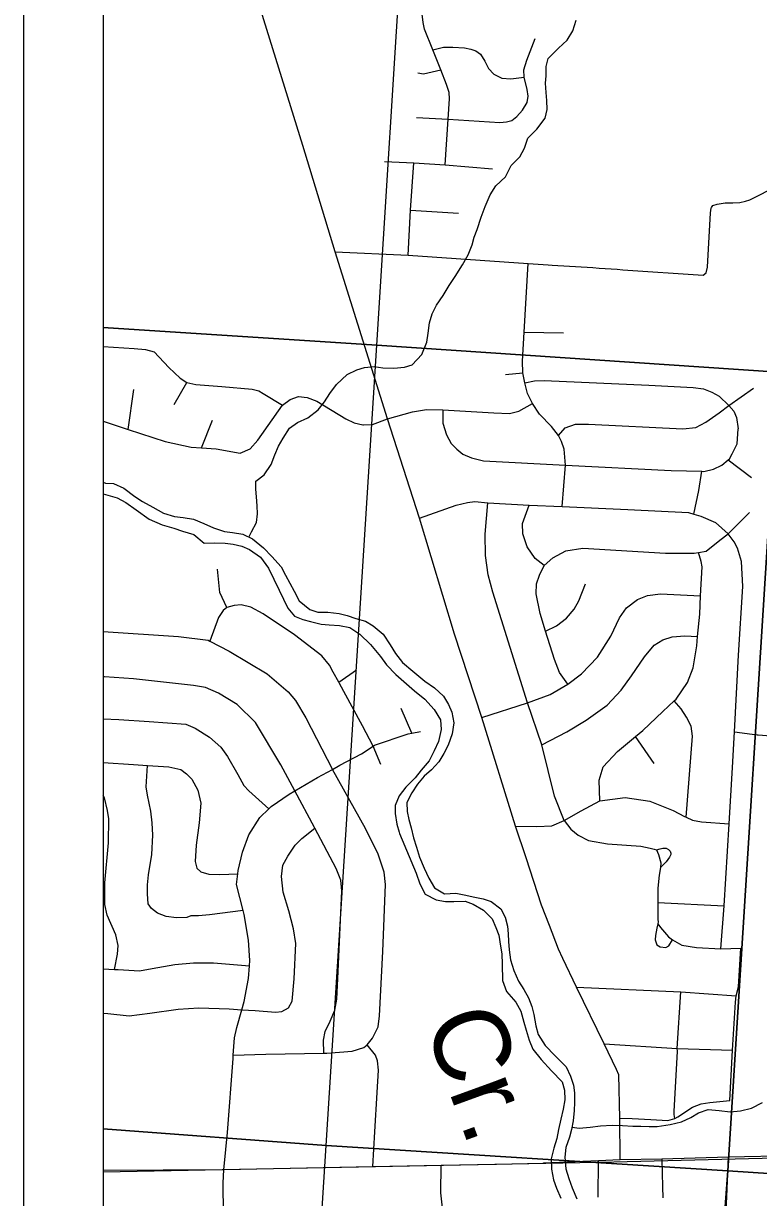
# Model space of a CAD drawing. Extents: x 0 to 34, y 0 to 22.
# Drawn here: x 2 to 2.921, y 19.283 to 20.754 of the extents above; entities that cross this region are included whole.
import ezdxf

# ---------------------------------------------------------------- set-up
doc = ezdxf.new("R2010")
doc.units = 0
for name, color, linetype in [('GM_X_City_Street', 7, 'Continuous'), ('GM_X_Corporation', 7, 'Continuous'), ('GM_X_County_Road', 7, 'Continuous'), ('GM_X_Minor_River', 7, 'Continuous'), ('GM_X_Minor_River_Text', 7, 'Continuous'), ('GM_X_Rail_Line', 7, 'Continuous'), ('GM_X_State_Route', 7, 'Continuous'), ('GM_X_Township_Road', 7, 'Continuous'), ('GM_X_US_Route', 7, 'Continuous'), ('SH_Data', 7, 'Continuous')]:
    doc.layers.add(name, color=color, linetype=linetype)

msp = doc.modelspace()

# ---------------------------------------------------------------- linework, layer by layer
at = {"layer": 'GM_X_City_Street'}
for p, q in [((2.4923, 20.6359), (2.5319, 20.6335)), ((2.485, 20.5198), (2.5451, 20.5157)), ((2.6272, 20.3667), (2.6764, 20.366)), ((2.6039, 20.3136), (2.6255, 20.316)), ((2.1888, 20.2761), (2.2045, 20.3035)), ((2.1313, 20.245), (2.1382, 20.2948)), ((2.8837, 20.275), (2.9145, 20.2967)), ((2.2231, 20.2218), (2.2369, 20.2565)), ((2.883, 20.207), (2.9121, 20.1847)), ((2.8829, 20.1141), (2.9096, 20.1408)), ((2.3949, 19.9284), (2.4171, 19.9438)), ((2.4864, 19.8644), (2.4731, 19.8953)), ((2.7901, 19.8263), (2.7668, 19.8601)), ((2.4479, 19.8249), (2.4382, 19.848)), ((2.7948, 19.6522), (2.8777, 19.6478)), ((2.72, 19.2831), (2.7206, 19.3289)), ((2.8811, 19.2837), (2.8832, 19.3334)), ((2.8794, 19.244), (2.8811, 19.2837))]:
    msp.add_line(p, q, dxfattribs=at)
for points in [[(2.5283, 20.5763), (2.5319, 20.6335), (2.5338, 20.6593), (2.5332, 20.6669), (2.5301, 20.6771), (2.523, 20.6955), (2.513, 20.7205), (2.5023, 20.7462), (2.5007, 20.7549), (2.4996, 20.7652), (2.5015, 20.7814), (2.4997, 20.8003), (2.5032, 20.8192)], [(2.5319, 20.6335), (2.5968, 20.6293), (2.605, 20.6301), (2.6118, 20.632), (2.6181, 20.637), (2.6252, 20.6448), (2.631, 20.6546), (2.6323, 20.6624), (2.6312, 20.6708), (2.6273, 20.6863), (2.627, 20.6953), (2.6307, 20.7074), (2.641, 20.7345)], [(2.513, 20.7205), (2.5264, 20.7239), (2.538, 20.7239), (2.5527, 20.7231), (2.5606, 20.7213), (2.5669, 20.7192), (2.5727, 20.715), (2.5779, 20.7063), (2.5826, 20.6971), (2.5892, 20.69), (2.5994, 20.685), (2.6105, 20.6842), (2.6273, 20.6863)], [(2.4939, 20.6915), (2.5012, 20.6905), (2.523, 20.6955)], [(2.4525, 20.5805), (2.4889, 20.5789), (2.5283, 20.5763), (2.5876, 20.5716)], [(2.4818, 20.4634), (2.485, 20.5198), (2.4889, 20.5789)], [(2.6749, 20.1482), (2.679, 20.2), (2.6774, 20.2201), (2.6741, 20.2299), (2.6704, 20.2372), (2.6615, 20.2486), (2.6463, 20.2642), (2.6378, 20.2772), (2.6316, 20.2899), (2.628, 20.3034), (2.6255, 20.316), (2.6251, 20.3303), (2.6272, 20.3667), (2.6325, 20.4528)], [(2.1, 20.3486), (2.1387, 20.3464), (2.153, 20.3449), (2.1636, 20.342), (2.182, 20.3226), (2.1964, 20.3093), (2.2045, 20.3035), (2.2159, 20.3012), (2.2483, 20.2985), (2.2865, 20.2953), (2.2947, 20.2932), (2.3003, 20.29), (2.3246, 20.2752)], [(2.628, 20.3034), (2.6402, 20.3058), (2.6525, 20.3062), (2.7834, 20.3003), (2.8392, 20.2974), (2.8521, 20.2956), (2.8625, 20.2915), (2.8715, 20.2864), (2.8837, 20.275), (2.89, 20.2678), (2.8932, 20.26), (2.8955, 20.2455)], [(2.1, 20.2554), (2.1313, 20.245), (2.1775, 20.2296), (2.2102, 20.2227), (2.2231, 20.2218), (2.2416, 20.2204), (2.2715, 20.2152), (2.2841, 20.2205), (2.2935, 20.2315), (2.3246, 20.2752), (2.334, 20.2825), (2.3446, 20.2862), (2.3556, 20.285), (2.3674, 20.2805), (2.4038, 20.258), (2.4144, 20.2531), (2.425, 20.2507), (2.426, 20.2507)], [(2.4561, 20.258), (2.4875, 20.267), (2.5051, 20.2699), (2.5255, 20.2695), (2.5892, 20.2658), (2.6088, 20.265), (2.6206, 20.2678), (2.6378, 20.2772)], [(2.6704, 20.2372), (2.6785, 20.2471), (2.6918, 20.2514), (2.7077, 20.2513), (2.8259, 20.2457), (2.8422, 20.2472), (2.8548, 20.2538), (2.8714, 20.2655), (2.8837, 20.275)], [(2.426, 20.2507), (2.4373, 20.2511), (2.4561, 20.258)], [(2.5255, 20.2695), (2.5255, 20.2527), (2.53, 20.238), (2.5357, 20.2274), (2.543, 20.2201), (2.5504, 20.2139), (2.5611, 20.2094), (2.5765, 20.2054), (2.679, 20.2), (2.8114, 20.1933), (2.85, 20.1924), (2.8526, 20.1923), (2.8644, 20.195), (2.8751, 20.2001), (2.883, 20.207), (2.8844, 20.2082), (2.8879, 20.2142), (2.8943, 20.2269), (2.8955, 20.2455)], [(2.8398, 20.1388), (2.846, 20.1682), (2.85, 20.1924)], [(2.4961, 20.1339), (2.5422, 20.1498), (2.5561, 20.1535), (2.5655, 20.1547), (2.5818, 20.1531), (2.6337, 20.1502), (2.6749, 20.1482), (2.7573, 20.1445), (2.8332, 20.1408), (2.8398, 20.1388), (2.8486, 20.1362), (2.8669, 20.1281), (2.8829, 20.1141)], [(2.6772, 19.7548), (2.6651, 19.7853), (2.6496, 19.8497), (2.6316, 19.9024), (2.5879, 20.0408), (2.5822, 20.0628), (2.579, 20.0869), (2.5786, 20.1135), (2.5818, 20.1531)], [(2.6524, 20.0743), (2.6409, 20.0833), (2.631, 20.0976), (2.6258, 20.114), (2.6253, 20.127), (2.6337, 20.1502)], [(2.6524, 20.0743), (2.6632, 20.0842), (2.6793, 20.0929), (2.701, 20.0962), (2.8044, 20.0898), (2.8403, 20.0897), (2.8459, 20.0907), (2.8555, 20.0924), (2.8725, 20.106), (2.8829, 20.1141)], [(2.8738, 19.5941), (2.8777, 19.6478), (2.884, 19.7506), (2.8883, 19.8212), (2.8907, 19.8659), (2.8958, 19.9619), (2.9013, 20.0479), (2.8994, 20.0795), (2.8945, 20.0963), (2.8902, 20.104), (2.8829, 20.1141)], [(2.722, 19.7794), (2.7212, 19.8056), (2.7261, 19.8222), (2.7444, 19.8415), (2.7668, 19.8601), (2.776, 19.8676), (2.8011, 19.8913), (2.8154, 19.9047), (2.8178, 19.9068), (2.8319, 19.9278), (2.8391, 19.9462), (2.8436, 19.9738), (2.8446, 19.9856), (2.8472, 20.0136), (2.8483, 20.0363), (2.8501, 20.0727), (2.8491, 20.0796), (2.8459, 20.0907)], [(2.2549, 20.0216), (2.2459, 20.0407), (2.2432, 20.0697)], [(2.6819, 19.9256), (2.6715, 19.9405), (2.6651, 19.9566), (2.6541, 19.992), (2.6472, 20.0144), (2.6425, 20.0388), (2.6428, 20.0513), (2.6465, 20.0622), (2.6524, 20.0743)], [(2.6541, 19.992), (2.668, 19.9987), (2.6803, 20.0086), (2.69, 20.0198), (2.6956, 20.0303), (2.704, 20.0513)], [(2.5741, 19.884), (2.6316, 19.9024), (2.6598, 19.9126), (2.6819, 19.9256), (2.699, 19.9387), (2.719, 19.9595), (2.7358, 19.9857), (2.7468, 20.0089), (2.7554, 20.0212), (2.7693, 20.0318), (2.7819, 20.0367), (2.7983, 20.0391), (2.8483, 20.0363)], [(2.4382, 19.848), (2.4249, 19.8734), (2.4119, 19.8972), (2.3959, 19.9265), (2.3949, 19.9284), (2.388, 19.9407), (2.3833, 19.9496), (2.3737, 19.9612), (2.3396, 19.9875), (2.3005, 20.0139), (2.2848, 20.0223), (2.2728, 20.0252), (2.2641, 20.0243), (2.2549, 20.0216), (2.2503, 20.0182), (2.2444, 20.0092), (2.2334, 19.9796)], [(2.1, 19.9919), (2.1943, 19.9854), (2.2313, 19.9807), (2.2334, 19.9796), (2.2578, 19.9671), (2.3055, 19.9386), (2.3318, 19.9163), (2.341, 19.9051), (2.3537, 19.8835), (2.387, 19.819)], [(2.6496, 19.8497), (2.6807, 19.8658), (2.7049, 19.8808), (2.7314, 19.8995), (2.7489, 19.9184), (2.7618, 19.936), (2.7782, 19.9599), (2.7903, 19.9744), (2.801, 19.9813), (2.8128, 19.9852), (2.8284, 19.9863), (2.8446, 19.9856)], [(2.3762, 19.4635), (2.3758, 19.4796), (2.3779, 19.4906), (2.3843, 19.5037), (2.3899, 19.5173), (2.3925, 19.5312), (2.3941, 19.5658), (2.3988, 19.667), (2.3976, 19.68), (2.3919, 19.6949), (2.3649, 19.7452), (2.3644, 19.7461), (2.3399, 19.792), (2.3224, 19.8246), (2.2908, 19.8778), (2.2679, 19.9004), (2.2444, 19.9143), (2.228, 19.9216), (2.2129, 19.9242), (2.1379, 19.9325), (2.1016, 19.935), (2.1, 19.9348)], [(2.8301, 19.7591), (2.8382, 19.8604), (2.8366, 19.873), (2.8308, 19.8845), (2.8239, 19.8949), (2.8154, 19.9047)], [(2.1, 19.8825), (2.1196, 19.8813), (2.1574, 19.8789), (2.2034, 19.8755), (2.215, 19.8706), (2.2329, 19.8595), (2.2473, 19.8466), (2.2554, 19.835), (2.2684, 19.8127), (2.2761, 19.7988), (2.2823, 19.7922), (2.3072, 19.7695)], [(2.8907, 19.8659), (2.9193, 19.8623), (2.9203, 19.8621), (2.9365, 19.861), (2.9444, 19.8604), (2.9653, 19.8622), (2.9741, 19.8665), (2.9811, 19.8739)], [(2.2509, 19.2245), (2.2501, 19.3005), (2.2511, 19.3175), (2.2514, 19.3213), (2.2554, 19.3642), (2.2625, 19.4566), (2.2628, 19.4607), (2.2643, 19.4828), (2.2673, 19.4956), (2.2735, 19.5179), (2.2764, 19.5281), (2.282, 19.5568), (2.2831, 19.5727), (2.2836, 19.5795), (2.282, 19.605), (2.2763, 19.6371), (2.2751, 19.642), (2.267, 19.6749), (2.2685, 19.688), (2.269, 19.6923), (2.2744, 19.7153), (2.2825, 19.7368), (2.2963, 19.7585), (2.3072, 19.7695), (2.3102, 19.7725), (2.3329, 19.7879), (2.3399, 19.792), (2.3685, 19.8087), (2.387, 19.819), (2.3965, 19.8243), (2.4233, 19.8385), (2.4382, 19.848), (2.4398, 19.8491), (2.4821, 19.8636), (2.4864, 19.8644), (2.4973, 19.8666)], [(2.1, 19.8275), (2.1379, 19.8251), (2.1553, 19.8239), (2.1821, 19.8221), (2.1971, 19.8187), (2.2042, 19.8132), (2.2108, 19.8069), (2.2184, 19.7931), (2.2222, 19.7766), (2.2201, 19.752), (2.2164, 19.724), (2.2152, 19.7035), (2.2172, 19.6951), (2.2224, 19.6908), (2.2322, 19.6875), (2.2458, 19.6872), (2.2685, 19.688)], [(2.2751, 19.642), (2.2332, 19.6366), (2.2192, 19.6354), (2.2097, 19.6353), (2.2048, 19.6335), (2.1919, 19.6331), (2.1787, 19.6346), (2.1679, 19.639), (2.1604, 19.6445), (2.1564, 19.6507), (2.1552, 19.6629), (2.1555, 19.6743), (2.1565, 19.6868), (2.1606, 19.7125), (2.1619, 19.7364), (2.1611, 19.752), (2.1596, 19.7668), (2.1555, 19.7867), (2.1535, 19.797), (2.1553, 19.8239)], [(2.4308, 19.4737), (2.4374, 19.4823), (2.4442, 19.4962), (2.4461, 19.5102), (2.4503, 19.5906), (2.4534, 19.6748), (2.4519, 19.69), (2.4445, 19.7126), (2.4283, 19.7449), (2.387, 19.819)], [(2.114, 19.5683), (2.1179, 19.5875), (2.1185, 19.5981), (2.1158, 19.6118), (2.1047, 19.6364), (2.102, 19.6498), (2.1019, 19.6767), (2.1065, 19.7271), (2.1068, 19.7571), (2.1052, 19.7674), (2.1014, 19.7835), (2.1, 19.7868)], [(2.6165, 19.748), (2.6431, 19.7475), (2.662, 19.7482), (2.6772, 19.7548), (2.6987, 19.767), (2.722, 19.7794), (2.7539, 19.7839), (2.7848, 19.7793), (2.814, 19.7676), (2.8282, 19.76), (2.8301, 19.7591), (2.8383, 19.7552), (2.8496, 19.7534), (2.884, 19.7506)], [(2.1, 19.5134), (2.1055, 19.513), (2.1326, 19.51), (2.1581, 19.5136), (2.1937, 19.5187), (2.2195, 19.5204), (2.2576, 19.519), (2.2735, 19.5179), (2.2901, 19.5167), (2.3157, 19.5149), (2.3237, 19.5155), (2.3321, 19.5202), (2.3365, 19.5285), (2.339, 19.5565), (2.3412, 19.6009), (2.3383, 19.6192), (2.3324, 19.6417), (2.3254, 19.6651), (2.3232, 19.6849), (2.3251, 19.6989), (2.331, 19.7101), (2.3404, 19.7239), (2.3486, 19.7325), (2.3649, 19.7452)], [(2.6772, 19.7548), (2.6857, 19.7442), (2.695, 19.7367), (2.708, 19.73), (2.7318, 19.7256), (2.7736, 19.7226), (2.7853, 19.7203), (2.79, 19.7191), (2.793, 19.7181), (2.7976, 19.7194), (2.8011, 19.7201), (2.8029, 19.7203), (2.8053, 19.7201), (2.8082, 19.7185), (2.8102, 19.7164), (2.8111, 19.7138), (2.8112, 19.7122), (2.8092, 19.7088), (2.805, 19.7031), (2.8026, 19.7006), (2.7983, 19.6962)], [(2.793, 19.7181), (2.7955, 19.7125), (2.7984, 19.702), (2.7983, 19.6962), (2.7966, 19.6864), (2.7947, 19.6701), (2.7948, 19.6522), (2.7949, 19.6462), (2.7949, 19.631), (2.7952, 19.6279), (2.7946, 19.6253), (2.7935, 19.62), (2.7918, 19.6109), (2.7916, 19.6052), (2.7937, 19.5991), (2.7978, 19.5967), (2.8046, 19.5958), (2.8085, 19.598), (2.8132, 19.6054)], [(2.7946, 19.6253), (2.798, 19.621), (2.8058, 19.6121), (2.808, 19.609), (2.8132, 19.6054), (2.8247, 19.5987), (2.8432, 19.5956), (2.8738, 19.5941), (2.8987, 19.5949)], [(2.8848, 19.4042), (2.8881, 19.467), (2.8922, 19.5271), (2.893, 19.5352), (2.8959, 19.5467), (2.8987, 19.5949)], [(2.1, 19.5691), (2.114, 19.5683), (2.1185, 19.5681), (2.1453, 19.5667), (2.1613, 19.5693), (2.1898, 19.5747), (2.2129, 19.5767), (2.2382, 19.5765), (2.2831, 19.5727)], [(2.6929, 19.5463), (2.8236, 19.5401), (2.893, 19.5352)], [(2.8162, 19.3815), (2.8151, 19.3867), (2.8152, 19.3903), (2.8192, 19.4659), (2.819, 19.4691), (2.8236, 19.5401)], [(2.2628, 19.4607), (2.3035, 19.4621), (2.3762, 19.4635), (2.3799, 19.4636), (2.4117, 19.4658), (2.4266, 19.4704), (2.4308, 19.4737)], [(2.4377, 19.3214), (2.4403, 19.3649), (2.443, 19.4142), (2.4448, 19.4422), (2.4436, 19.454), (2.4411, 19.4609), (2.4308, 19.4737)], [(2.7276, 19.4749), (2.819, 19.4691), (2.8881, 19.467)], [(2.747, 19.3821), (2.7624, 19.3814), (2.7859, 19.3801), (2.8073, 19.379), (2.8162, 19.3815), (2.8199, 19.3835), (2.8384, 19.3956), (2.8491, 19.3999), (2.8597, 19.4015), (2.8848, 19.4042)], [(2.525, 19.2698), (2.5227, 19.2884), (2.5232, 19.3231)]]:
    msp.add_lwpolyline(points, dxfattribs=at)
at = {"layer": 'GM_X_Corporation'}
for points in [[(4.3071, 20.9), (2.1, 20.9), (2.1, 14.1), (3.0169, 14.1), (3.0406, 14.4484), (3.1026, 15.287), (3.1745, 16.2606), (2.934, 16.2765), (2.366, 16.3159), (2.2862, 16.3208), (2.1768, 16.323), (2.2478, 17.3472), (2.3155, 18.3567), (3.8153, 18.2543), (3.8503, 18.7566), (3.8611, 18.9124), (3.8924, 19.3621), (3.9019, 19.4987), (3.9133, 19.6628), (3.9816, 20.645), (3.9912, 20.7822), (4.2975, 20.7549)], [(2.1177, 20.9), (2.1, 20.9), (2.1, 20.3725), (2.4427, 20.3504), (2.4759, 20.8769), (2.3657, 20.8848)], [(2.4759, 20.8769), (3.2845, 20.8293), (3.4815, 20.8174), (3.4452, 20.283), (2.9456, 20.3167), (2.4427, 20.3504)], [(2.1, 20.3725), (2.1, 19.3686), (2.3794, 19.3479), (2.4427, 20.3504)], [(2.4427, 20.3504), (2.9456, 20.3167), (2.8825, 19.3159), (2.3794, 19.3479)], [(2.9456, 20.3167), (3.4452, 20.283), (3.3789, 19.2835), (2.8825, 19.3159)], [(2.1, 19.3686), (2.1, 18.3755), (2.3165, 18.3624), (2.3794, 19.3479)], [(2.3794, 19.3479), (2.8825, 19.3159), (2.8093, 18.3281), (2.3165, 18.3624)], [(2.8825, 19.3159), (3.3789, 19.2835), (3.3148, 18.2914), (2.8093, 18.3281)]]:
    msp.add_lwpolyline(points, close=True, dxfattribs=at)
for points in [[(3.8151, 18.2549), (3.8501, 18.7572), (3.8609, 18.9129), (3.8918, 19.3576), (3.8924, 19.3656), (3.9015, 19.4967), (3.9015, 19.497), (3.9131, 19.6633), (3.9131, 19.6638), (3.9335, 19.9563), (3.9417, 20.0742), (3.9814, 20.6455), (3.9909, 20.7828), (4.2973, 20.7554), (4.3068, 20.9), (2.1, 20.9), (2.1, 14.1)], [(3.8151, 18.2549), (3.8501, 18.7572), (3.8609, 18.9129), (3.8918, 19.3576), (3.8924, 19.3656), (3.9015, 19.4967), (3.9015, 19.497), (3.9131, 19.6633), (3.9131, 19.6638), (3.9335, 19.9563), (3.9417, 20.0742), (3.9814, 20.6455), (3.9909, 20.7828), (3.2798, 20.8248), (2.7336, 20.8606), (2.2596, 20.8916), (2.1, 20.8993), (2.1, 16.3272)], [(2.1, 20.8991), (2.1, 17.7516)]]:
    msp.add_lwpolyline(points, dxfattribs=at)
at = {"layer": 'GM_X_County_Road'}
msp.add_line((2.7475, 19.3301), (2.747, 19.3821), dxfattribs=at)
for points in [[(2.6759, 19.582), (2.6704, 19.5936), (2.659, 19.6234), (2.6492, 19.6488), (2.63, 19.708), (2.6165, 19.748), (2.5741, 19.884), (2.5402, 19.9885), (2.4961, 20.1339), (2.4561, 20.258), (2.3903, 20.4675), (2.3499, 20.6006), (2.2823, 20.8191), (2.2616, 20.8854)], [(2.747, 19.3821), (2.746, 19.4364), (2.743, 19.443), (2.7276, 19.4749), (2.6929, 19.5463), (2.6759, 19.582)]]:
    msp.add_lwpolyline(points, dxfattribs=at)
at = {"layer": 'GM_X_Minor_River'}
for points in [[(2.2825, 20.11), (2.2856, 20.1166), (2.2921, 20.1283), (2.2933, 20.1393), (2.2926, 20.1492), (2.2919, 20.1606), (2.2912, 20.1701), (2.2909, 20.1799), (2.3016, 20.1882), (2.3103, 20.2011), (2.315, 20.2132), (2.3196, 20.2238), (2.3253, 20.234), (2.3333, 20.2465), (2.3432, 20.2536), (2.3561, 20.2596), (2.3694, 20.2694), (2.377, 20.2796), (2.3839, 20.2898), (2.3923, 20.3011), (2.4056, 20.3136), (2.4177, 20.3196), (2.4272, 20.3225), (2.4393, 20.3236), (2.4503, 20.322), (2.4639, 20.3215), (2.4775, 20.323), (2.487, 20.326), (2.4991, 20.3388), (2.5053, 20.3543), (2.5069, 20.3653), (2.5085, 20.3786), (2.5119, 20.3896), (2.5173, 20.4005), (2.5257, 20.4126), (2.5333, 20.4251), (2.541, 20.4364), (2.5501, 20.4512), (2.557, 20.4637), (2.562, 20.4761), (2.5647, 20.4856), (2.5682, 20.4955), (2.5736, 20.511), (2.5786, 20.5242), (2.5847, 20.539), (2.5916, 20.55), (2.6038, 20.5613), (2.611, 20.5756), (2.6217, 20.5866), (2.6278, 20.5972), (2.6317, 20.6097), (2.6431, 20.621), (2.6537, 20.635), (2.6561, 20.6459), (2.6558, 20.657), (2.6547, 20.6672), (2.654, 20.6786), (2.6548, 20.6881), (2.6549, 20.6998), (2.6572, 20.7097), (2.6705, 20.7225), (2.6812, 20.7327), (2.6881, 20.7444), (2.6923, 20.7577)], [(2.1, 20.1789), (2.1026, 20.1777), (2.1128, 20.1772), (2.1256, 20.1711), (2.1395, 20.1608), (2.1493, 20.1546), (2.1621, 20.1473), (2.1753, 20.14), (2.1893, 20.1358), (2.1999, 20.1346), (2.2131, 20.1326), (2.2259, 20.1272), (2.238, 20.1214), (2.252, 20.1172), (2.2618, 20.1156), (2.275, 20.1136), (2.2871, 20.1079), (2.3006, 20.0964), (2.3111, 20.0857), (2.3228, 20.0727), (2.3284, 20.0621), (2.3336, 20.0522), (2.3392, 20.0423), (2.3452, 20.0301), (2.3588, 20.0194), (2.3686, 20.0159), (2.3814, 20.0158), (2.3954, 20.0142), (2.4056, 20.0119), (2.4165, 20.008), (2.4283, 20.0045), (2.438, 19.9988), (2.4505, 19.9884), (2.4595, 19.9751), (2.4662, 19.9641), (2.4748, 19.953), (2.488, 19.9419), (2.5027, 19.9293), (2.5151, 19.9212), (2.5264, 19.9106), (2.5327, 19.9003), (2.5368, 19.8908), (2.539, 19.8771), (2.5371, 19.8634), (2.5321, 19.8494), (2.5267, 19.8388), (2.5202, 19.8286), (2.5114, 19.8184), (2.5019, 19.8105), (2.4936, 19.8003), (2.4867, 19.7897), (2.4802, 19.7776), (2.4809, 19.7662), (2.4827, 19.756), (2.4857, 19.7457), (2.4886, 19.7332), (2.4923, 19.7214), (2.496, 19.7088), (2.502, 19.6951), (2.508, 19.6826), (2.5151, 19.6704), (2.5275, 19.6631), (2.5415, 19.6638), (2.5521, 19.6618), (2.5653, 19.6587), (2.5759, 19.6567), (2.5861, 19.6536), (2.5981, 19.6441), (2.6033, 19.6338), (2.6063, 19.6224), (2.6074, 19.6129), (2.6077, 19.6034), (2.6084, 19.5928), (2.6102, 19.5803), (2.6143, 19.5669), (2.6202, 19.5536), (2.627, 19.5433), (2.6326, 19.5327), (2.6367, 19.522)], [(2.1, 20.1642), (2.1172, 20.159), (2.1281, 20.1532), (2.1413, 20.144), (2.1575, 20.1326), (2.1737, 20.1253), (2.1885, 20.121), (2.1994, 20.1175), (2.2134, 20.1132), (2.2265, 20.1022), (2.2398, 20.1028), (2.2526, 20.1024), (2.2628, 20.1012), (2.2734, 20.0988), (2.2832, 20.0946), (2.2968, 20.085), (2.3069, 20.0709), (2.3203, 20.0435), (2.3259, 20.0321), (2.3312, 20.0211), (2.3394, 20.0111), (2.35, 20.0069), (2.3598, 20.0042), (2.373, 20.0007), (2.3828, 19.9999), (2.3961, 19.9994), (2.4089, 19.9967), (2.4213, 19.9882), (2.4349, 19.9756), (2.4473, 19.9604), (2.4548, 19.9501), (2.4664, 19.9379), (2.48, 19.926), (2.4901, 19.9172), (2.5029, 19.9069), (2.5146, 19.8939), (2.5224, 19.881), (2.5235, 19.8688), (2.52, 19.854), (2.5146, 19.8423), (2.5081, 19.8295), (2.4982, 19.8181), (2.4906, 19.8083), (2.4792, 19.7966), (2.4708, 19.786), (2.4658, 19.7739), (2.4657, 19.7637), (2.4679, 19.7504), (2.4705, 19.7405), (2.471, 19.7386)], [(2.471, 19.7386), (2.4921, 19.6891), (2.4966, 19.6754), (2.5033, 19.6625), (2.5172, 19.6556), (2.5286, 19.6536), (2.5392, 19.6536), (2.5532, 19.6538), (2.5633, 19.65), (2.5765, 19.6427), (2.5871, 19.6316), (2.5919, 19.621), (2.5956, 19.6111), (2.5978, 19.5974), (2.5993, 19.5879), (2.5996, 19.575), (2.6002, 19.5545), (2.605, 19.5408), (2.617, 19.5275), (2.623, 19.516), (2.6267, 19.5023), (2.6297, 19.4921), (2.6334, 19.4799), (2.6382, 19.4685), (2.6484, 19.4555), (2.6615, 19.4414), (2.6747, 19.4277), (2.678, 19.417), (2.6783, 19.4049), (2.676, 19.3931), (2.6732, 19.3806), (2.6701, 19.3677), (2.6682, 19.3564), (2.6643, 19.3442), (2.6612, 19.331), (2.6615, 19.3181), (2.6641, 19.3048), (2.6678, 19.2941), (2.6734, 19.2819)], [(2.6367, 19.522), (2.6393, 19.5118), (2.6418, 19.4977), (2.6448, 19.4867), (2.6534, 19.473), (2.6662, 19.46), (2.6801, 19.4462), (2.6853, 19.4344), (2.689, 19.4234), (2.6905, 19.4139), (2.6904, 19.4018), (2.69, 19.3915), (2.6887, 19.3786), (2.6868, 19.3676), (2.6841, 19.3582), (2.6795, 19.3453), (2.6782, 19.3331), (2.6797, 19.3183), (2.6834, 19.3065), (2.6875, 19.2948), (2.6931, 19.2811)], [(2.6873, 19.3705), (2.6962, 19.3695), (2.7099, 19.3709), (2.7231, 19.3723), (2.7375, 19.373), (2.7503, 19.3726), (2.7636, 19.3721), (2.7734, 19.372), (2.784, 19.3716), (2.7938, 19.3715), (2.8101, 19.3741), (2.8245, 19.3774), (2.8362, 19.3827), (2.8457, 19.3887), (2.8579, 19.3928), (2.8718, 19.3915), (2.8855, 19.3899), (2.8983, 19.391), (2.912, 19.3947), (2.926, 19.4015)]]:
    msp.add_lwpolyline(points, dxfattribs=at)
at = {"layer": 'GM_X_Rail_Line'}
msp.add_lwpolyline([(2.1, 19.3147), (2.7397, 19.3273), (3.8879, 19.3555)], dxfattribs=at)
at = {"layer": 'GM_X_State_Route'}
msp.add_lwpolyline([(2.7996, 19.3309), (2.8005, 19.2959), (2.8011, 19.282)], dxfattribs=at)
at = {"layer": 'GM_X_Township_Road'}
for points in [[(2.8621, 20.5228), (2.8638, 20.5253), (2.8692, 20.5272), (2.879, 20.5287), (2.8889, 20.529), (2.8973, 20.5294), (2.9046, 20.5307), (2.9101, 20.5327), (2.9454, 20.5504), (2.964, 20.5592), (2.9715, 20.5621)], [(2.7509, 20.445), (2.8515, 20.4383), (2.8554, 20.4409), (2.8571, 20.4482), (2.8608, 20.5162), (2.8615, 20.522), (2.8621, 20.5228)], [(2.3903, 20.4675), (2.4818, 20.4634), (2.6325, 20.4528), (2.6575, 20.4511), (2.6624, 20.4508)], [(2.6624, 20.4508), (2.7133, 20.4476), (2.7212, 20.447)], [(2.7212, 20.447), (2.744, 20.4455), (2.7509, 20.445)]]:
    msp.add_lwpolyline(points, dxfattribs=at)
at = {"layer": 'GM_X_US_Route'}
msp.add_line((2.6519, 19.3258), (2.6912, 19.3276), dxfattribs=at)
for points in [[(2.6912, 19.3276), (2.7206, 19.3289), (2.7475, 19.3301), (2.7996, 19.3309), (2.8832, 19.3334), (2.964, 19.3351), (3.1485, 19.3393), (3.2328, 19.3413), (3.2844, 19.3434)], [(2.1, 19.3167), (2.25, 19.3175), (2.2511, 19.3175), (2.4377, 19.3214), (2.5232, 19.3231), (2.5926, 19.3245), (2.6509, 19.3257), (2.6519, 19.3258)]]:
    msp.add_lwpolyline(points, dxfattribs=at)
at = {"layer": 'SH_Data'}
for p, q in [((2, 21), (2, 14)), ((2.1, 20.9), (2.1, 14.1))]:
    msp.add_line(p, q, dxfattribs=at)

# ---------------------------------------------------------------- texts
at = {"layer": 'GM_X_Minor_River_Text'}
msp.add_text('Cr.', height=0.0947, rotation=289.9992, dxfattribs=at).set_placement((2.5012, 19.5024))

doc.saveas('drawing.dxf')
